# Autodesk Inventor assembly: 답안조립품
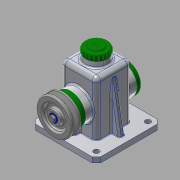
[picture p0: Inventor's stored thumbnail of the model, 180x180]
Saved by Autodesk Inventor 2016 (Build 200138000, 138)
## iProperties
Created: 2018-10
Part Number: 답안조립품
Material: 일반
Document SubType Name: Assembly
Designer: user
Author: user
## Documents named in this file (14)
- C:\Users\user\Desktop\481016V1014\답안조립품.iam
- C:\Users\user\Desktop\481016V1014\본체.ipt
- C:\Users\user\Desktop\481016V1014\뒤커버.ipt
- C:\Users\user\Desktop\481016V1014\상부캡.ipt
- C:\Users\user\Desktop\481016V1014\앞커버.ipt
- C:\Users\user\Desktop\481016V1014\베어링 15 x 35 x 11.ipt
- C:\Users\user\Desktop\481016V1014\축.ipt
- C:\Users\user\Desktop\481016V1014\오일실 15 25 7.ipt
- C:\Users\user\Desktop\481016V1014\멈춤링 15 x 1.ipt
- C:\Users\user\Desktop\481016V1014\키 5 x 5 x 14.ipt
- C:\Users\user\Desktop\481016V1014\V-벨트풀리.ipt
- C:\Users\user\Desktop\481016V1014\볼트 M6 x 12.ipt
- C:\Users\user\Desktop\481016V1014\와셔.ipt
- C:\Users\user\Desktop\481016V1014\볼트 M4 x 10.ipt
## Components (1 placed, 1 different names)
1. V-벨트풀리:1 — 각도:1
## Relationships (1: Angle 1)
- 각도:1 [Angle]: V-벨트풀리:1
